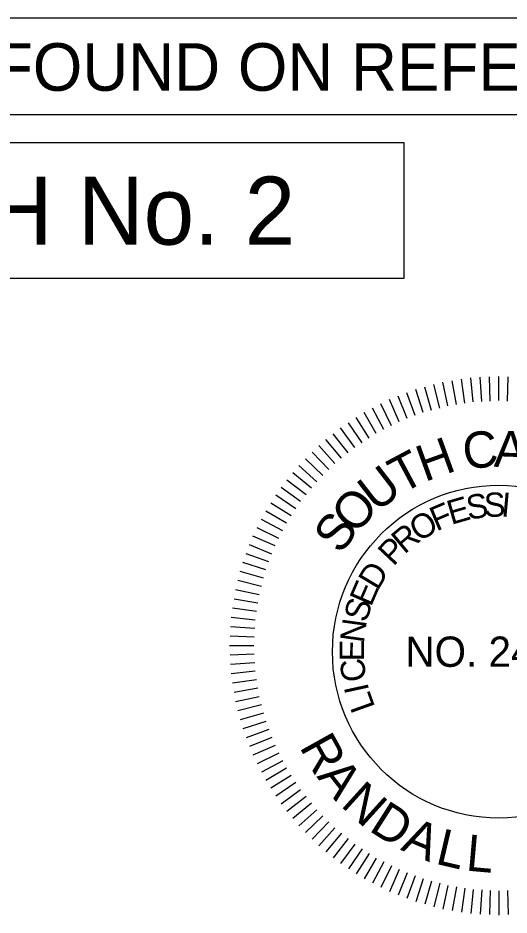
# Model space of a CAD drawing. Extents: x 1964377 to 1966966, y 1116414 to 1123213.
# Drawn here: x 1966800.7 to 1966872.9, y 1122586.1 to 1122718 of the extents above; entities that cross this region are included whole.
import ezdxf

# ---------------------------------------------------------------- set-up
doc = ezdxf.new("R2010")
doc.units = 0
for name, color, linetype in [('RD_Sketch1', 7, 'Continuous'), ('RD_TX_Misc2', 7, 'Continuous'), ('RD_TX_PEShield', 7, 'Continuous')]:
    doc.layers.add(name, color=color, linetype=linetype)

msp = doc.modelspace()

# ---------------------------------------------------------------- linework, layer by layer
at = {"layer": 'RD_Sketch1'}
msp.add_lwpolyline([(1966650.5, 1122717.98), (1966950.92, 1122717.98), (1966950.92, 1122703.72), (1966650.5, 1122703.72)], close=True, dxfattribs=at)
at = {"layer": 'RD_TX_Misc2'}
msp.add_lwpolyline([(1966696.27, 1122699.65), (1966857.47, 1122699.65), (1966857.47, 1122679.65), (1966696.27, 1122679.65)], close=True, dxfattribs=at)
at = {"layer": 'RD_TX_PEShield'}
for p, q in [((1966865.2, 1122661.13), (1966864.58, 1122664.63)), ((1966865.2, 1122661.13), (1966864.58, 1122664.63)), ((1966866.44, 1122661.33), (1966865.94, 1122664.85)), ((1966866.44, 1122661.33), (1966865.94, 1122664.85)), ((1966867.68, 1122661.52), (1966867.31, 1122665.06)), ((1966867.68, 1122661.52), (1966867.31, 1122665.06)), ((1966868.94, 1122661.59), (1966868.69, 1122665.14)), ((1966868.94, 1122661.59), (1966868.69, 1122665.14)), ((1966870.19, 1122661.65), (1966870.07, 1122665.21)), ((1966870.19, 1122661.65), (1966870.07, 1122665.21)), ((1966871.45, 1122661.72), (1966871.45, 1122665.28)), ((1966871.45, 1122661.72), (1966871.45, 1122665.28)), ((1966872.7, 1122661.65), (1966872.83, 1122665.21)), ((1966872.7, 1122661.65), (1966872.83, 1122665.21)), ((1966860.31, 1122659.96), (1966859.21, 1122663.34)), ((1966860.31, 1122659.96), (1966859.21, 1122663.34)), ((1966861.52, 1122660.28), (1966860.54, 1122663.7)), ((1966861.52, 1122660.28), (1966860.54, 1122663.7)), ((1966862.74, 1122660.61), (1966861.88, 1122664.06)), ((1966862.74, 1122660.61), (1966861.88, 1122664.06)), ((1966863.95, 1122660.93), (1966863.21, 1122664.41)), ((1966863.95, 1122660.93), (1966863.21, 1122664.41)), ((1966857.96, 1122659.06), (1966856.63, 1122662.35)), ((1966857.96, 1122659.06), (1966856.63, 1122662.35)), ((1966859.13, 1122659.51), (1966857.92, 1122662.85)), ((1966859.13, 1122659.51), (1966857.92, 1122662.85)), ((1966855.66, 1122658.03), (1966854.11, 1122661.23)), ((1966855.66, 1122658.03), (1966854.11, 1122661.23)), ((1966856.79, 1122658.6), (1966855.34, 1122661.86)), ((1966856.79, 1122658.6), (1966855.34, 1122661.86)), ((1966853.42, 1122656.89), (1966851.64, 1122659.97)), ((1966853.42, 1122656.89), (1966851.64, 1122659.97)), ((1966854.55, 1122657.46), (1966852.88, 1122660.6)), ((1966854.55, 1122657.46), (1966852.88, 1122660.6)), ((1966851.32, 1122655.52), (1966849.33, 1122658.47)), ((1966851.32, 1122655.52), (1966849.33, 1122658.47)), ((1966852.37, 1122656.21), (1966850.48, 1122659.22)), ((1966852.37, 1122656.21), (1966850.48, 1122659.22)), ((1966849.28, 1122654.04), (1966847.09, 1122656.85)), ((1966849.28, 1122654.04), (1966847.09, 1122656.85)), ((1966850.26, 1122654.84), (1966848.17, 1122657.72)), ((1966850.26, 1122654.84), (1966848.17, 1122657.72)), ((1966848.31, 1122653.25), (1966846.02, 1122655.98)), ((1966848.31, 1122653.25), (1966846.02, 1122655.98)), ((1966846.44, 1122651.57), (1966843.97, 1122654.13)), ((1966846.44, 1122651.57), (1966843.97, 1122654.13)), ((1966847.33, 1122652.46), (1966844.95, 1122655.11)), ((1966847.33, 1122652.46), (1966844.95, 1122655.11)), ((1966845.55, 1122650.68), (1966842.99, 1122653.15)), ((1966845.55, 1122650.68), (1966842.99, 1122653.15)), ((1966844.66, 1122649.79), (1966842.01, 1122652.18)), ((1966844.66, 1122649.79), (1966842.01, 1122652.18)), ((1966843.87, 1122648.82), (1966841.14, 1122651.1)), ((1966843.87, 1122648.82), (1966841.14, 1122651.1)), ((1966842.29, 1122646.86), (1966839.41, 1122648.95)), ((1966842.29, 1122646.86), (1966839.41, 1122648.95)), ((1966843.08, 1122647.84), (1966840.28, 1122650.03)), ((1966843.08, 1122647.84), (1966840.28, 1122650.03)), ((1966841.6, 1122645.81), (1966838.65, 1122647.8)), ((1966841.6, 1122645.81), (1966838.65, 1122647.8)), ((1966840.92, 1122644.75), (1966837.9, 1122646.64)), ((1966840.92, 1122644.75), (1966837.9, 1122646.64)), ((1966840.23, 1122643.7), (1966837.15, 1122645.48)), ((1966840.23, 1122643.7), (1966837.15, 1122645.48)), ((1966839.66, 1122642.58), (1966836.52, 1122644.25)), ((1966839.66, 1122642.58), (1966836.52, 1122644.25)), ((1966839.09, 1122641.46), (1966835.89, 1122643.02)), ((1966839.09, 1122641.46), (1966835.89, 1122643.02)), ((1966838.52, 1122640.34), (1966835.27, 1122641.78)), ((1966838.52, 1122640.34), (1966835.27, 1122641.78)), ((1966838.07, 1122639.16), (1966834.77, 1122640.49)), ((1966838.07, 1122639.16), (1966834.77, 1122640.49)), ((1966837.62, 1122637.99), (1966834.28, 1122639.2)), ((1966837.62, 1122637.99), (1966834.28, 1122639.2)), ((1966837.17, 1122636.81), (1966833.78, 1122637.91)), ((1966837.17, 1122636.81), (1966833.78, 1122637.91)), ((1966836.84, 1122635.6), (1966833.42, 1122636.58)), ((1966836.84, 1122635.6), (1966833.42, 1122636.58)), ((1966836.52, 1122634.38), (1966833.07, 1122635.25)), ((1966836.52, 1122634.38), (1966833.07, 1122635.25)), ((1966836.19, 1122633.17), (1966832.71, 1122633.91)), ((1966836.19, 1122633.17), (1966832.71, 1122633.91)), ((1966835.99, 1122631.93), (1966832.49, 1122632.54)), ((1966835.99, 1122631.93), (1966832.49, 1122632.54)), ((1966835.8, 1122630.69), (1966832.27, 1122631.18)), ((1966835.8, 1122630.69), (1966832.27, 1122631.18)), ((1966835.6, 1122629.44), (1966832.06, 1122629.82)), ((1966835.6, 1122629.44), (1966832.06, 1122629.82)), ((1966835.53, 1122628.19), (1966831.99, 1122628.43)), ((1966835.53, 1122628.19), (1966831.99, 1122628.43)), ((1966835.47, 1122626.93), (1966831.91, 1122627.06)), ((1966835.47, 1122626.93), (1966831.91, 1122627.06)), ((1966835.4, 1122625.68), (1966831.84, 1122625.68)), ((1966835.4, 1122625.68), (1966831.84, 1122625.68)), ((1966835.47, 1122624.42), (1966831.91, 1122624.29)), ((1966835.47, 1122624.42), (1966831.91, 1122624.29)), ((1966835.53, 1122623.16), (1966831.99, 1122622.92)), ((1966835.53, 1122623.16), (1966831.99, 1122622.92)), ((1966835.6, 1122621.91), (1966832.06, 1122621.54)), ((1966835.6, 1122621.91), (1966832.06, 1122621.54)), ((1966835.8, 1122620.67), (1966832.27, 1122620.17)), ((1966835.8, 1122620.67), (1966832.27, 1122620.17)), ((1966835.99, 1122619.42), (1966832.49, 1122618.81)), ((1966835.99, 1122619.42), (1966832.49, 1122618.81)), ((1966836.19, 1122618.18), (1966832.71, 1122617.44)), ((1966836.19, 1122618.18), (1966832.71, 1122617.44)), ((1966836.52, 1122616.97), (1966833.07, 1122616.11)), ((1966836.52, 1122616.97), (1966833.07, 1122616.11)), ((1966836.84, 1122615.75), (1966833.42, 1122614.77)), ((1966836.84, 1122615.75), (1966833.42, 1122614.77)), ((1966837.17, 1122614.54), (1966833.78, 1122613.44)), ((1966837.62, 1122613.36), (1966834.28, 1122612.15)), ((1966837.62, 1122613.36), (1966834.28, 1122612.15)), ((1966838.07, 1122612.19), (1966834.77, 1122610.86)), ((1966838.07, 1122612.19), (1966834.77, 1122610.86)), ((1966838.52, 1122611.01), (1966835.27, 1122609.57)), ((1966838.52, 1122611.01), (1966835.27, 1122609.57)), ((1966839.09, 1122609.89), (1966835.89, 1122608.33)), ((1966839.09, 1122609.89), (1966835.89, 1122608.33)), ((1966839.66, 1122608.77), (1966836.52, 1122607.1)), ((1966839.66, 1122608.77), (1966836.52, 1122607.1)), ((1966840.23, 1122607.65), (1966837.15, 1122605.87)), ((1966840.23, 1122607.65), (1966837.15, 1122605.87)), ((1966840.92, 1122606.6), (1966837.9, 1122604.71)), ((1966840.92, 1122606.6), (1966837.9, 1122604.71)), ((1966841.6, 1122605.54), (1966838.65, 1122603.56)), ((1966841.6, 1122605.54), (1966838.65, 1122603.56)), ((1966842.29, 1122604.49), (1966839.41, 1122602.4)), ((1966842.29, 1122604.49), (1966839.41, 1122602.4)), ((1966843.08, 1122603.51), (1966840.28, 1122601.32)), ((1966843.08, 1122603.51), (1966840.28, 1122601.32)), ((1966843.87, 1122602.53), (1966841.14, 1122600.25)), ((1966843.87, 1122602.53), (1966841.14, 1122600.25)), ((1966844.66, 1122601.56), (1966842.01, 1122599.17)), ((1966844.66, 1122601.56), (1966842.01, 1122599.17)), ((1966845.55, 1122600.67), (1966842.99, 1122598.2)), ((1966845.55, 1122600.67), (1966842.99, 1122598.2)), ((1966846.44, 1122599.78), (1966843.97, 1122597.22)), ((1966846.44, 1122599.78), (1966843.97, 1122597.22)), ((1966847.33, 1122598.89), (1966844.95, 1122596.24)), ((1966847.33, 1122598.89), (1966844.95, 1122596.24)), ((1966848.31, 1122598.1), (1966846.02, 1122595.37)), ((1966848.31, 1122598.1), (1966846.02, 1122595.37)), ((1966849.28, 1122597.31), (1966847.09, 1122594.5)), ((1966849.28, 1122597.31), (1966847.09, 1122594.5)), ((1966850.26, 1122596.51), (1966848.17, 1122593.63)), ((1966850.26, 1122596.51), (1966848.17, 1122593.63)), ((1966851.32, 1122595.83), (1966849.33, 1122592.88)), ((1966851.32, 1122595.83), (1966849.33, 1122592.88)), ((1966852.37, 1122595.14), (1966850.48, 1122592.13)), ((1966852.37, 1122595.14), (1966850.48, 1122592.13)), ((1966853.42, 1122594.46), (1966851.64, 1122591.38)), ((1966853.42, 1122594.46), (1966851.64, 1122591.38)), ((1966854.55, 1122593.89), (1966852.88, 1122590.75)), ((1966854.55, 1122593.89), (1966852.88, 1122590.75)), ((1966855.66, 1122593.32), (1966854.11, 1122590.12)), ((1966855.66, 1122593.32), (1966854.11, 1122590.12)), ((1966856.79, 1122592.75), (1966855.34, 1122589.49)), ((1966856.79, 1122592.75), (1966855.34, 1122589.49)), ((1966857.96, 1122592.3), (1966856.63, 1122589)), ((1966857.96, 1122592.3), (1966856.63, 1122589)), ((1966859.13, 1122591.85), (1966857.92, 1122588.5)), ((1966859.13, 1122591.85), (1966857.92, 1122588.5)), ((1966860.31, 1122591.39), (1966859.21, 1122588.01)), ((1966860.31, 1122591.39), (1966859.21, 1122588.01)), ((1966861.52, 1122591.07), (1966860.54, 1122587.65)), ((1966861.52, 1122591.07), (1966860.54, 1122587.65)), ((1966862.74, 1122590.74), (1966861.88, 1122587.29)), ((1966862.74, 1122590.74), (1966861.88, 1122587.29)), ((1966863.95, 1122590.42), (1966863.21, 1122586.94)), ((1966863.95, 1122590.42), (1966863.21, 1122586.94)), ((1966865.2, 1122590.22), (1966864.58, 1122586.72)), ((1966865.2, 1122590.22), (1966864.58, 1122586.72)), ((1966866.44, 1122590.02), (1966865.94, 1122586.5)), ((1966866.44, 1122590.02), (1966865.94, 1122586.5)), ((1966867.68, 1122589.83), (1966867.31, 1122586.29)), ((1966867.68, 1122589.83), (1966867.31, 1122586.29)), ((1966868.94, 1122589.76), (1966868.69, 1122586.22)), ((1966868.94, 1122589.76), (1966868.69, 1122586.22)), ((1966870.19, 1122589.7), (1966870.07, 1122586.14)), ((1966870.19, 1122589.7), (1966870.07, 1122586.14)), ((1966871.45, 1122589.63), (1966871.45, 1122586.07)), ((1966871.45, 1122589.63), (1966871.45, 1122586.07)), ((1966872.7, 1122589.7), (1966872.83, 1122586.14)), ((1966872.7, 1122589.7), (1966872.83, 1122586.14))]:
    msp.add_line(p, q, dxfattribs=at)
msp.add_circle((1966871.45, 1122624.8), 24.48, dxfattribs=at)

# ---------------------------------------------------------------- texts
at = {"layer": 'RD_Sketch1'}
msp.add_text('ALIGNMENT CONTROL CAN BE FOUND ON REFERENCE SHEET', height=7, dxfattribs=at).set_placement((1966654.15, 1122707.27))
at = {"layer": 'RD_TX_Misc2'}
msp.add_text('OUTFALL DITCH No. 2', height=10, dxfattribs=at).set_placement((1966701.06, 1122684.65))
at = {"layer": 'RD_TX_PEShield'}
for s, height, rotation, p in [('C', 5.34, 6.8832, (1966866.44, 1122651.54)), ('A', 5.34, 357.9448, (1966870.66, 1122651.99)), ('H', 5.34, 19.9102, (1966860.54, 1122649.72)), ('T', 5.34, 28.0947, (1966857.11, 1122647.91)), ('U', 5.34, 37.7726, (1966853.42, 1122645.17)), ('O', 5.34, 47.4504, (1966850.26, 1122641.85)), ('E', 3.56, 16.1843, (1966864.44, 1122643.43)), ('S', 3.56, 8.6909, (1966866.93, 1122644.19)), ('S', 3.56, 1.79, (1966869.3, 1122644.59)), ('I', 3.56, 354.889, (1966871.69, 1122644.7)), ('F', 3.56, 23.0853, (1966862.26, 1122642.46)), ('S', 5.34, 54.9027, (1966848.22, 1122638.96)), ('O', 3.56, 31.7869, (1966859.69, 1122640.86)), ('R', 3.56, 39.8902, (1966857.54, 1122639.04)), ('P', 3.56, 46.7912, (1966855.93, 1122637.27)), ('D', 3.56, 59.074, (1966853.63, 1122633.68)), ('E', 3.56, 66.5674, (1966852.63, 1122631.29)), ('S', 3.56, 73.4683, (1966851.98, 1122628.98)), ('N', 3.56, 82.17, (1966851.58, 1122625.98)), ('E', 3.56, 89.6633, (1966851.59, 1122623.38)), ('C', 3.56, 97.7667, (1966851.99, 1122620.6)), ('I', 3.56, 102.2511, (1966852.38, 1122619.09)), ('L', 3.56, 109.7445, (1966853.28, 1122616.65)), ('R', 5.34, 299.1493, (1966842.04, 1122610.82)), ('A', 5.34, 308.0877, (1966844.57, 1122606.42)), ('N', 5.34, 317.7655, (1966848.04, 1122602.17)), ('D', 5.34, 327.4433, (1966852.18, 1122598.56)), ('A', 5.34, 337.1212, (1966856.87, 1122595.69)), ('L', 5.34, 346.799, (1966861.97, 1122593.65)), ('L', 5.34, 354.9835, (1966866.5, 1122592.62))]:
    msp.add_text(s, height=height, rotation=rotation, dxfattribs=at).set_placement(p)
msp.add_text('NO. 24265', height=4.45, dxfattribs=at).set_placement((1966857.69, 1122622.57))

doc.saveas('drawing.dxf')
